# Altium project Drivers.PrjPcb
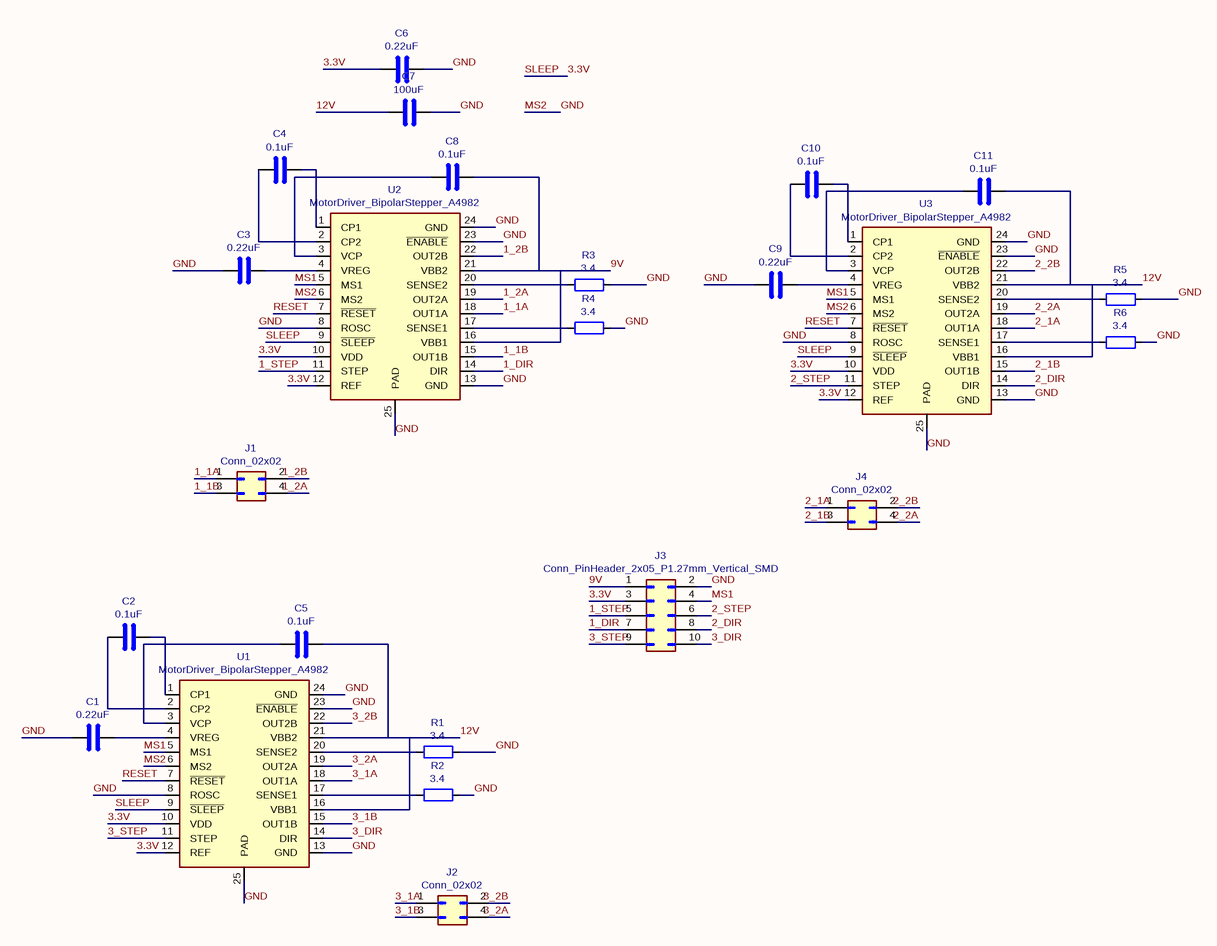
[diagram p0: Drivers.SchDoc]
1 sheet, 24 parts. Net scope: global (net labels, ports and power ports of the same name join across sheets).
Board files: Drivers.PcbDoc, Drivers(1).PcbDoc

## Sheet Drivers.SchDoc
size 297 x 210 mm

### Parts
C1  0.22uF  [C_1206]
C2  0.1uF  [C_1206]
C3  0.22uF  [C_1206]
C4  0.1uF  [C_1206]
C5  0.1uF  [C_1206]
C6  0.22uF  [C_1206]
C7  100uF  [C_1206]
C8  0.1uF  [C_1206]
C9  0.22uF  [C_1206]
C10  0.1uF  [C_1206]
C11  0.1uF  [C_1206]
J1  Conn_02x02  [PinHeader_2x02_P1.27mm_Vertical_SMD]
J2  Conn_02x02  [PinHeader_2x02_P1.27mm_Vertical_SMD]
J3  Conn_PinHeader_2x05_P1.27mm_Vertical_SMD  [PinHeader_2x05_P1.27mm_Vertical_SMD]
J4  Conn_02x02  [PinHeader_2x02_P1.27mm_Vertical_SMD]
R1  3.4  [R_1206]
R2  3.4  [R_1206]
R3  3.4  [R_1206]
R4  3.4  [R_1206]
R5  3.4  [R_1206]
R6  3.4  [R_1206]
U1  MotorDriver_BipolarStepper_A4982  [24-TSSOP-EP]
U2  MotorDriver_BipolarStepper_A4982  [24-TSSOP-EP]
U3  MotorDriver_BipolarStepper_A4982  [24-TSSOP-EP]

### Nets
1_1A: J1.1(Pin_1) U2.18(OUT1A)
1_1B: J1.3(Pin_3) U2.15(OUT1B)
1_2A: J1.4(Pin_4) U2.19(OUT2A)
1_2B: J1.2(Pin_2) U2.22(OUT2B)
1_DIR: J3.7(Pin_7) U2.14(DIR)
1_STEP: J3.5(Pin_5) U2.11(STEP)
2_1A: J4.1(Pin_1) U3.18(OUT1A)
2_1B: J4.3(Pin_3) U3.15(OUT1B)
2_2A: J4.4(Pin_4) U3.19(OUT2A)
2_2B: J4.2(Pin_2) U3.22(OUT2B)
2_DIR: J3.8(Pin_8) U3.14(DIR)
2_STEP: J3.6(Pin_6) U3.11(STEP)
3.3V: C6.2 J3.3(Pin_3) U1.9(~{SLEEP}) U1.10(VDD) U1.12(REF) U2.9(~{SLEEP}) U2.10(VDD) U2.12(REF) U3.9(~{SLEEP}) U3.10(VDD) U3.12(REF)  [also labelled SLEEP]
3_1A: J2.1(Pin_1) U1.18(OUT1A)
3_1B: J2.3(Pin_3) U1.15(OUT1B)
3_2A: J2.4(Pin_4) U1.19(OUT2A)
3_2B: J2.2(Pin_2) U1.22(OUT2B)
3_DIR: J3.10(Pin_10) U1.14(DIR)
3_STEP: J3.9(Pin_9) U1.11(STEP)
9V: C8.1 J3.1(Pin_1) U2.16(VBB1) U2.21(VBB2)
12V: C5.1 C7.2 C11.1 U1.16(VBB1) U1.21(VBB2) U3.16(VBB1) U3.21(VBB2)
GND: C1.2 C3.2 C6.1 C7.1 C9.2 J3.2(Pin_2) R1.2 R2.1 R3.2 R4.1 R5.2 R6.1 U1.6(MS2) U1.8(ROSC) U1.13(GND) U1.23(~{ENABLE}) U1.24(GND) U1.25(PAD) U2.6(MS2) U2.8(ROSC) U2.13(GND) U2.23(~{ENABLE}) U2.24(GND) U2.25(PAD) U3.6(MS2) U3.8(ROSC) U3.13(GND) U3.23(~{ENABLE}) U3.24(GND) U3.25(PAD)  [also labelled MS2]
MS1: J3.4(Pin_4) U1.5(MS1) U2.5(MS1) U3.5(MS1)
RESET: U1.7(~{RESET}) U2.7(~{RESET}) U3.7(~{RESET})
NetC1_1: C1.1 U1.4(VREG)
NetC2_1: C2.1 U1.1(CP1)
NetC2_2: C2.2 U1.2(CP2)
NetC3_1: C3.1 U2.4(VREG)
NetC4_1: C4.1 U2.1(CP1)
NetC4_2: C4.2 U2.2(CP2)
NetC5_2: C5.2 U1.3(VCP)
NetC8_2: C8.2 U2.3(VCP)
NetC9_1: C9.1 U3.4(VREG)
NetC10_1: C10.1 U3.1(CP1)
NetC10_2: C10.2 U3.2(CP2)
NetC11_2: C11.2 U3.3(VCP)
NetR1_1: R1.1 U1.20(SENSE2)
NetR2_2: R2.2 U1.17(SENSE1)
NetR3_1: R3.1 U2.20(SENSE2)
NetR4_2: R4.2 U2.17(SENSE1)
NetR5_1: R5.1 U3.20(SENSE2)
NetR6_2: R6.2 U3.17(SENSE1)

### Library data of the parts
C1-C11 = C
J1 J2 J4 = Conn_PinHeader_2x02_P1.27mm_Vertical_SMD
R1-R6 = R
